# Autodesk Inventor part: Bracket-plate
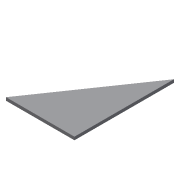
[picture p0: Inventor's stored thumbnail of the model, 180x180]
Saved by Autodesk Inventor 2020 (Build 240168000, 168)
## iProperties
Part Number: Bracket-plate
Document SubType Name: Modeling
Created: 2003-01
Designer: Owner
Density: 1 g/cm^3
Material: Generic
Appearance: Default
Control State: 0
Master: False
Checked Out: False
Shininess: 64.0
Length Units: 11269
Angle Units: 11279
Time Units: 11290
Mass Units: 11283
Length Display Precision: 3
Angle Display Precision: 2
Compacted: True
Density: 0.0
Volumn: 0.0
Area: 0.0
PropertySet Name: Model Information
Author: Owner
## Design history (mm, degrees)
sketch "Sketch1"
  geometry: L1 (-27.627, 0.004)-(-0.127, 0.004); L2 (-0.127, 0.004)-(-0.127, 40.004); L3 (-0.127, 40.004)-(-27.627, 0.004)
  constraints: 6 end point, 1 horizontal, 1 perpendicular
  dimensions: "d0" = 27.5 distance of L1.start L1.end; "d1" = 40 distance of L1.end L2.end
extrude "Extrusion1" new body sketch "Sketch1" distance "d2" = 1.25; taper "d3" = 0 deg
body "Solid1"
